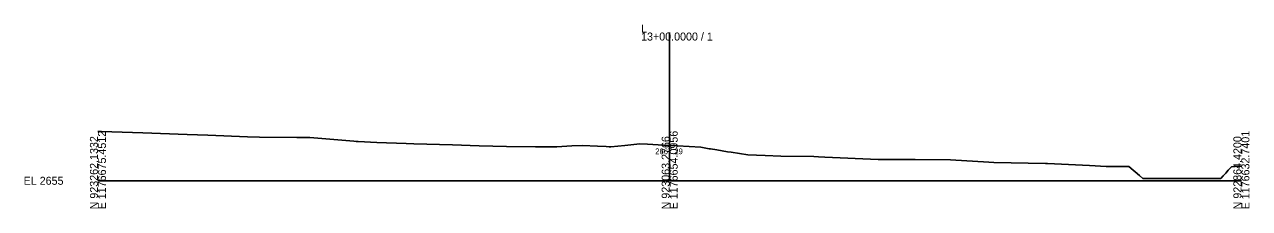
# Model space of a CAD drawing. Extents: x -26 to 1403, y -10 to 9563.
# Drawn here: x -25.7 to 402.8, y 2990.3 to 3054.6 of the extents above; entities that cross this region are included whole.
import ezdxf

# ---------------------------------------------------------------- set-up
doc = ezdxf.new("R2010")
doc.units = 0
for name, color, linetype in [('Exist Cross Section Cell', 7, 'Continuous'), ('Exist XS Center Line Elevation Label', 7, 'Continuous'), ('Exist XS Ground Line', 7, 'Continuous')]:
    doc.layers.add(name, color=color, linetype=linetype)

msp = doc.modelspace()

# ---------------------------------------------------------------- linework, layer by layer
at = {"layer": 'Exist Cross Section Cell'}
for p, q in [((200, 3000), (200, 3051.84)), ((0, 3000), (200, 3000)), ((200, 3000), (400, 3000))]:
    msp.add_line(p, q, dxfattribs=at)
at = {"layer": 'Exist XS Ground Line'}
for p, q in [((0, 3017.28), (1.22, 3017.24)), ((1.22, 3017.24), (15.66, 3016.78)), ((15.66, 3016.78), (31.25, 3016.15)), ((31.25, 3016.15), (38.39, 3015.96)), ((38.39, 3015.96), (52.33, 3015.41)), ((52.33, 3015.41), (56.51, 3015.2)), ((56.51, 3015.2), (69.55, 3015.16)), ((69.55, 3015.16), (74.15, 3015.17)), ((74.15, 3015.17), (89.52, 3013.85)), ((89.52, 3013.85), (90.34, 3013.77)), ((90.34, 3013.77), (91.07, 3013.74)), ((91.07, 3013.74), (97.58, 3013.44)), ((97.58, 3013.44), (107.88, 3013)), ((107.88, 3013), (110.46, 3012.92)), ((110.46, 3012.92), (124.08, 3012.55)), ((184.28, 3012.36), (189.62, 3012.91)), ((189.62, 3012.91), (192.2, 3012.76)), ((192.2, 3012.76), (199.66, 3012.31)), ((124.08, 3012.55), (133.36, 3012.24)), ((133.36, 3012.24), (142.92, 3011.94)), ((142.92, 3011.94), (153.11, 3011.88)), ((153.11, 3011.88), (160.5, 3011.88)), ((160.5, 3011.88), (165.73, 3012.2)), ((165.73, 3012.2), (169.47, 3012.34)), ((169.47, 3012.34), (174.72, 3012.13)), ((174.72, 3012.13), (177.82, 3011.99)), ((177.82, 3011.99), (178.78, 3011.91)), ((178.78, 3011.91), (179.43, 3011.86)), ((179.43, 3011.86), (184.28, 3012.36)), ((199.66, 3012.31), (200, 3012.29)), ((200, 3012.29), (202.72, 3012.16)), ((202.72, 3012.16), (210.94, 3011.73)), ((210.94, 3011.73), (213.83, 3011.21)), ((213.83, 3011.21), (214.24, 3011.14)), ((214.24, 3011.14), (216.49, 3010.77)), ((216.49, 3010.77), (220.24, 3010.16)), ((220.24, 3010.16), (221.49, 3009.97)), ((221.49, 3009.97), (227.39, 3009.04)), ((227.39, 3009.04), (233.39, 3008.8)), ((233.39, 3008.8), (238.94, 3008.63)), ((238.94, 3008.63), (250.4, 3008.44)), ((250.4, 3008.44), (252.02, 3008.37)), ((252.02, 3008.37), (254.28, 3008.28)), ((254.28, 3008.28), (272.93, 3007.41)), ((272.93, 3007.41), (285.26, 3007.38)), ((285.26, 3007.38), (285.87, 3007.38)), ((285.87, 3007.38), (298.23, 3007.28)), ((298.23, 3007.28), (311.7, 3006.48)), ((311.7, 3006.48), (313.41, 3006.37)), ((313.41, 3006.37), (331.5, 3006.09)), ((331.5, 3006.09), (332.14, 3006.07)), ((332.14, 3006.07), (346.82, 3005.3)), ((346.82, 3005.3), (352.67, 3004.96)), ((352.67, 3004.96), (357.71, 3005)), ((357.71, 3005), (360.63, 3004.94)), ((360.63, 3004.94), (364.38, 3001.84)), ((395.37, 3003.65), (396.49, 3004.83)), ((396.49, 3004.83), (397.77, 3004.95)), ((397.77, 3004.95), (400, 3005.13)), ((364.38, 3001.84), (365.51, 3000.81)), ((365.51, 3000.81), (375.29, 3000.81)), ((375.29, 3000.81), (387.73, 3000.81)), ((387.73, 3000.81), (392.78, 3000.81)), ((392.78, 3000.81), (393.61, 3001.7)), ((393.61, 3001.7), (394.51, 3002.68)), ((394.51, 3002.68), (395.37, 3003.65))]:
    msp.add_line(p, q, dxfattribs=at)

# ---------------------------------------------------------------- texts
at = {"layer": 'Exist Cross Section Cell'}
for s, p in [('13+00.0000 / 1', (190, 3049.04)), ('L', (190, 3051.84)), ('EL 2655', (-26, 2998.6))]:
    msp.add_text(s, height=2.8, dxfattribs=at).set_placement(p)
for s, p in [('E 1176675.4512', (2.8, 2990)), ('E 1176654.0956', (202.8, 2990)), ('E 1176632.7401', (402.8, 2990)), ('N 923262.1332', (0, 2990)), ('N 923063.2766', (200, 2990)), ('N 922864.4200', (400, 2990))]:
    msp.add_text(s, height=2.8, rotation=90, dxfattribs=at).set_placement(p)
at = {"layer": 'Exist XS Center Line Elevation Label'}
msp.add_text('2667.29', height=2, dxfattribs=at).set_placement((194.94, 3009.29))

doc.saveas('drawing.dxf')
